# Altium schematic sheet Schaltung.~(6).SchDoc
size A4
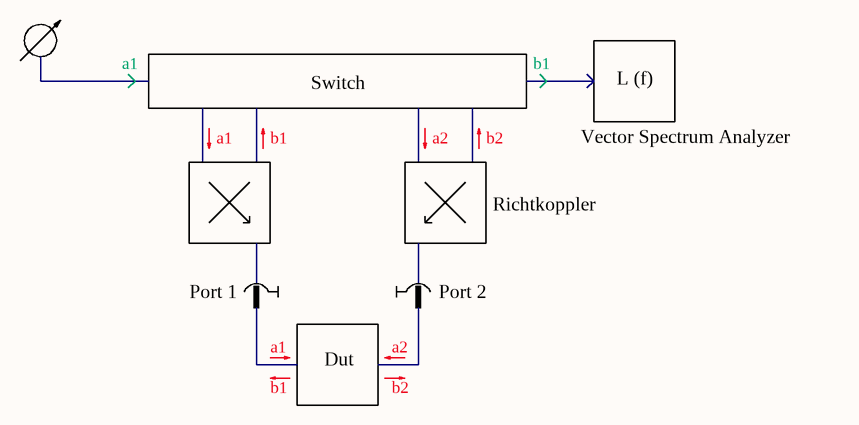
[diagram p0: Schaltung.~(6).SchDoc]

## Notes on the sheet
- a1
- Switch
- b1
- L (f)
- a2
- b2
- Vector Spectrum Analyzer
- Richtkoppler
- Port 1
- Port 2
- Dut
